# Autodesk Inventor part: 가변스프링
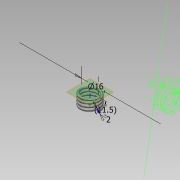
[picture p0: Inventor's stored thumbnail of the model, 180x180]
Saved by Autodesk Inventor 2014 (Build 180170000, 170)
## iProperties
Created: 2015-04
Part Number: 가변스프링
Material: 강철, 탄소
Document SubType Name: Modeling
Designer: Administrator
Density: 7.87 g/cm^3
Appearance: 반연마
Mass: 4.78551 g
Surface Area: 12.5277 cm^2
Volume: 0.60807 cm^3
Author: Administrator
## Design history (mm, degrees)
sketch "스케치1"
  geometry: L1 (0, 11.5)-(8, 11.5); L2 (8, 11.5)-(8, 0); L3 (8, 0)-(0, 0); L4 (0, 0)-(0, 11.5); C1 r 1 at (8, 0); 1 further point
  constraints: 8 end point, 2 coincident, 2 parallel, 1 centre point, 1 horizontal, 1 perpendicular
  dimensions: "d0" = 16 diameter of L2 L4; "d1" = 11.50049 distance between parallel lines of L3 L1 (derived); "d2" = 2 diameter of C1
feature "코일1" pitch "d3" = 10; turns "d5" = 4; dims "d4" = 11.50049 (= d1), "d6" = 0, angle "d7" = 90 deg, angle "d8" = 90 deg, "d9" = 0, "d10" = 0
sketch "스케치2"
  geometry: L1 (-9, 0)-(-7, 0) reference; 1 further point
  constraints: 1 horizontal alignment
extrude "돌출1" cut sketch "스케치2" stored distance "d11" = 10; taper "d12" = 0 deg
node "작업 평면1"
sketch "스케치3"
  geometry: L1 (9, 0)-(7, 0) reference; 1 further point
  constraints: 1 horizontal alignment
extrude "돌출2" cut sketch "스케치3" stored distance "d13" = 10; taper "d14" = 0 deg
node "솔리드1"
node "절단 모서리 투영1"
node "절단 모서리 투영2"
